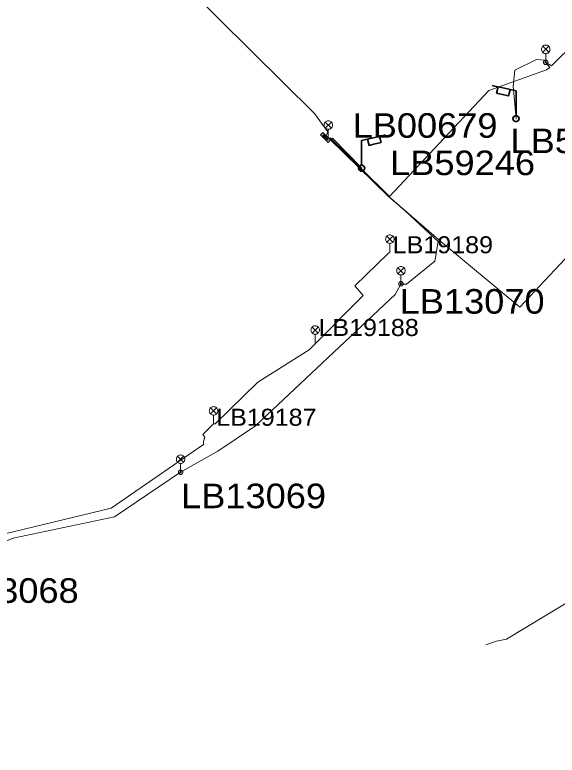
# Model space of a CAD drawing. Extents: x -688049 to -687261, y -973611 to -973038.
# Drawn here: x -687529.7 to -687482, y -973591.4 to -973526.2 of the extents above; entities that cross this region are included whole.
import ezdxf

# ---------------------------------------------------------------- set-up
doc = ezdxf.new("R2010")
doc.units = 0
doc.header["$LTSCALE"] = 0.87
doc.linetypes.add('LONG_DASH_SHORT_DASH', pattern=[9.9, 6, -1.2, 1.5, -1.2])
doc.layers.add('1', color=7, linetype='Continuous', lineweight=13)

msp = doc.modelspace()

# ---------------------------------------------------------------- hatches: boundary and pattern name
at = {"layer": '1'}
for points in [[(-687502.608, -973536.55), (-687501.932, -973537.217), (-687502.154, -973537.442), (-687502.83, -973536.776)], [(-687502.561, -973536.774), (-687502.156, -973537.173), (-687502.2, -973537.218), (-687502.606, -973536.819)]]:
    msp.add_hatch(color=256, dxfattribs=at).paths.add_polyline_path(points)

# ---------------------------------------------------------------- linework, layer by layer
for p, q in [((-687483.245, -973528.965), (-687482.715, -973529.495)), ((-687483.245, -973529.495), (-687482.715, -973528.965)), ((-687482.98, -973530.38), (-687482.98, -973529.605)), ((-687502.396, -973535.64), (-687501.866, -973536.17)), ((-687502.396, -973536.17), (-687501.866, -973535.64)), ((-687502.131, -973537.055), (-687502.131, -973536.28)), ((-687496.974, -973545.689), (-687496.444, -973546.219)), ((-687496.974, -973546.219), (-687496.444, -973545.689)), ((-687496.709, -973547.104), (-687496.709, -973546.329)), ((-687495.995, -973548.475), (-687495.465, -973549.005)), ((-687495.995, -973549.005), (-687495.465, -973548.475)), ((-687495.73, -973549.89), (-687495.73, -973549.115)), ((-687503.552, -973553.701), (-687503.022, -973554.231)), ((-687503.552, -973554.231), (-687503.022, -973553.701)), ((-687503.287, -973555.116), (-687503.287, -973554.341)), ((-687512.507, -973560.829), (-687511.977, -973561.359)), ((-687512.507, -973561.359), (-687511.977, -973560.829)), ((-687512.242, -973562.244), (-687512.242, -973561.469)), ((-687515.405, -973565.085), (-687514.875, -973565.615)), ((-687515.405, -973565.615), (-687514.875, -973565.085)), ((-687515.14, -973566.5), (-687515.14, -973565.725))]:
    msp.add_line(p, q, dxfattribs=at)
at = {"layer": '1', "lineweight": 35}
for p, q in [((-687485.57, -973535.34), (-687485.624, -973535.34)), ((-687499.224, -973539.7), (-687499.17, -973539.7))]:
    msp.add_line(p, q, dxfattribs=at)
at = {"layer": '1'}
for points in [[(-687467.405, -973515.295), (-687467.405, -973515.662), (-687469.111, -973517.285), (-687472.35, -973520.366), (-687478.189, -973526.459), (-687482.459, -973530.691), (-687482.98, -973530.38)], [(-687517.645, -973521.334), (-687517.314, -973521.125), (-687514.569, -973523.755), (-687503.343, -973534.873), (-687502.167, -973536.514), (-687502.381, -973536.996)], [(-687482.97, -973530.382), (-687482.626, -973530.839), (-687482.904, -973531.048), (-687487.979, -973532.871), (-687496.755, -973542.207), (-687501.975, -973537.02), (-687502.131, -973537.055)], [(-687480.925, -973547.385), (-687481.31, -973547.725), (-687485.252, -973551.938), (-687492.408, -973546.007), (-687496.766, -973542.227), (-687502.006, -973537.076), (-687502.131, -973537.055)], [(-687495.73, -973549.94), (-687495.244, -973549.94), (-687492.742, -973547.903), (-687492.441, -973546.165), (-687495.323, -973543.485), (-687496.865, -973542.174), (-687502.028, -973537.125), (-687502.131, -973537.055)], [(-687503.287, -973555.116), (-687503.226, -973555.116), (-687499.071, -973550.923), (-687499.792, -973550.062), (-687496.828, -973547.19), (-687496.709, -973547.104)], [(-687495.73, -973549.94), (-687496.256, -973550.822), (-687508.558, -973562.417), (-687511.878, -973564.636), (-687515.14, -973566.5)], [(-687512.242, -973562.244), (-687512.091, -973562.244), (-687508.337, -973558.555), (-687503.828, -973555.698), (-687503.28, -973555.178), (-687503.287, -973555.116)], [(-687512.242, -973562.244), (-687513.198, -973563.185), (-687513.014, -973563.421), (-687513.139, -973563.788), (-687513.139, -973564.053), (-687521.25, -973569.673), (-687531.507, -973572.146), (-687537.665, -973575.239), (-687557.082, -973591.297), (-687558.661, -973591.432), (-687559.419, -973591.073), (-687564.028, -973586.264), (-687565.766, -973584.462), (-687569.052, -973581.162), (-687571.096, -973578.384), (-687572.639, -973577), (-687572.732, -973575.503), (-687572.487, -973574.726), (-687571.502, -973574.263), (-687570.41, -973574.56)], [(-687515.14, -973566.5), (-687520.976, -973570.433), (-687529.887, -973572.299), (-687535.528, -973574.583), (-687536.76, -973575.4)], [(-687488.25, -973581.7), (-687487.316, -973581.393), (-687486.449, -973581.213), (-687476.202, -973575.029), (-687473.932, -973573.292), (-687473.59, -973572.32)]]:
    msp.add_lwpolyline(points, dxfattribs=at)
for points in [[(-687482.605, -973529.23), (-687482.611, -973529.165), (-687482.628, -973529.102), (-687482.655, -973529.043), (-687482.693, -973528.989), (-687482.739, -973528.943), (-687482.792, -973528.905), (-687482.852, -973528.878), (-687482.915, -973528.861), (-687482.98, -973528.855), (-687483.045, -973528.861), (-687483.108, -973528.878), (-687483.168, -973528.905), (-687483.221, -973528.943), (-687483.267, -973528.989), (-687483.305, -973529.043), (-687483.332, -973529.102), (-687483.349, -973529.165), (-687483.355, -973529.23), (-687483.349, -973529.295), (-687483.332, -973529.358), (-687483.305, -973529.418), (-687483.267, -973529.471), (-687483.221, -973529.517), (-687483.168, -973529.555), (-687483.108, -973529.582), (-687483.045, -973529.599), (-687482.98, -973529.605), (-687482.915, -973529.599), (-687482.852, -973529.582), (-687482.792, -973529.555), (-687482.739, -973529.517), (-687482.693, -973529.471), (-687482.655, -973529.418), (-687482.628, -973529.358), (-687482.611, -973529.295)], [(-687482.79, -973530.38), (-687482.793, -973530.347), (-687482.801, -973530.315), (-687482.815, -973530.285), (-687482.834, -973530.258), (-687482.858, -973530.234), (-687482.885, -973530.215), (-687482.915, -973530.201), (-687482.947, -973530.193), (-687482.98, -973530.19), (-687483.013, -973530.193), (-687483.045, -973530.201), (-687483.075, -973530.215), (-687483.102, -973530.234), (-687483.126, -973530.258), (-687483.145, -973530.285), (-687483.159, -973530.315), (-687483.167, -973530.347), (-687483.17, -973530.38), (-687483.167, -973530.413), (-687483.159, -973530.445), (-687483.145, -973530.475), (-687483.126, -973530.502), (-687483.102, -973530.526), (-687483.075, -973530.545), (-687483.045, -973530.559), (-687483.013, -973530.567), (-687482.98, -973530.57), (-687482.947, -973530.567), (-687482.915, -973530.559), (-687482.885, -973530.545), (-687482.858, -973530.526), (-687482.834, -973530.502), (-687482.815, -973530.475), (-687482.801, -973530.445), (-687482.793, -973530.413)], [(-687482.93, -973530.38), (-687482.931, -973530.371), (-687482.933, -973530.363), (-687482.937, -973530.355), (-687482.942, -973530.348), (-687482.948, -973530.342), (-687482.955, -973530.337), (-687482.963, -973530.333), (-687482.971, -973530.331), (-687482.98, -973530.33), (-687482.989, -973530.331), (-687482.997, -973530.333), (-687483.005, -973530.337), (-687483.012, -973530.342), (-687483.018, -973530.348), (-687483.023, -973530.355), (-687483.027, -973530.363), (-687483.029, -973530.371), (-687483.03, -973530.38), (-687483.029, -973530.389), (-687483.027, -973530.397), (-687483.023, -973530.405), (-687483.018, -973530.412), (-687483.012, -973530.418), (-687483.005, -973530.423), (-687482.997, -973530.427), (-687482.989, -973530.429), (-687482.98, -973530.43), (-687482.971, -973530.429), (-687482.963, -973530.427), (-687482.955, -973530.423), (-687482.948, -973530.418), (-687482.942, -973530.412), (-687482.937, -973530.405), (-687482.933, -973530.397), (-687482.931, -973530.389)], [(-687501.756, -973535.905), (-687501.762, -973535.84), (-687501.779, -973535.777), (-687501.806, -973535.718), (-687501.844, -973535.664), (-687501.89, -973535.618), (-687501.944, -973535.58), (-687502.003, -973535.553), (-687502.066, -973535.536), (-687502.131, -973535.53), (-687502.196, -973535.536), (-687502.259, -973535.553), (-687502.318, -973535.58), (-687502.372, -973535.618), (-687502.418, -973535.664), (-687502.456, -973535.718), (-687502.483, -973535.777), (-687502.5, -973535.84), (-687502.506, -973535.905), (-687502.5, -973535.97), (-687502.483, -973536.033), (-687502.456, -973536.093), (-687502.418, -973536.146), (-687502.372, -973536.192), (-687502.318, -973536.23), (-687502.259, -973536.257), (-687502.196, -973536.274), (-687502.131, -973536.28), (-687502.066, -973536.274), (-687502.003, -973536.257), (-687501.944, -973536.23), (-687501.89, -973536.192), (-687501.844, -973536.146), (-687501.806, -973536.093), (-687501.779, -973536.033), (-687501.762, -973535.97)], [(-687502.608, -973536.55), (-687501.932, -973537.217), (-687502.154, -973537.442), (-687502.83, -973536.776)], [(-687502.608, -973536.55), (-687501.932, -973537.217), (-687502.154, -973537.442), (-687502.83, -973536.776)], [(-687502.561, -973536.774), (-687502.156, -973537.173), (-687502.2, -973537.218), (-687502.606, -973536.819)], [(-687496.334, -973545.954), (-687496.34, -973545.889), (-687496.357, -973545.826), (-687496.384, -973545.766), (-687496.422, -973545.713), (-687496.468, -973545.667), (-687496.522, -973545.629), (-687496.581, -973545.602), (-687496.644, -973545.585), (-687496.709, -973545.579), (-687496.774, -973545.585), (-687496.837, -973545.602), (-687496.896, -973545.629), (-687496.95, -973545.667), (-687496.996, -973545.713), (-687497.034, -973545.766), (-687497.061, -973545.826), (-687497.078, -973545.889), (-687497.084, -973545.954), (-687497.078, -973546.019), (-687497.061, -973546.082), (-687497.034, -973546.142), (-687496.996, -973546.195), (-687496.95, -973546.241), (-687496.896, -973546.279), (-687496.837, -973546.306), (-687496.774, -973546.323), (-687496.709, -973546.329), (-687496.644, -973546.323), (-687496.581, -973546.306), (-687496.522, -973546.279), (-687496.468, -973546.241), (-687496.422, -973546.195), (-687496.384, -973546.142), (-687496.357, -973546.082), (-687496.34, -973546.019)], [(-687495.355, -973548.74), (-687495.361, -973548.675), (-687495.378, -973548.612), (-687495.405, -973548.552), (-687495.443, -973548.499), (-687495.489, -973548.453), (-687495.542, -973548.415), (-687495.602, -973548.388), (-687495.665, -973548.371), (-687495.73, -973548.365), (-687495.795, -973548.371), (-687495.858, -973548.388), (-687495.918, -973548.415), (-687495.971, -973548.453), (-687496.017, -973548.499), (-687496.055, -973548.552), (-687496.082, -973548.612), (-687496.099, -973548.675), (-687496.105, -973548.74), (-687496.099, -973548.805), (-687496.082, -973548.868), (-687496.055, -973548.928), (-687496.017, -973548.981), (-687495.971, -973549.027), (-687495.918, -973549.065), (-687495.858, -973549.092), (-687495.795, -973549.109), (-687495.73, -973549.115), (-687495.665, -973549.109), (-687495.602, -973549.092), (-687495.542, -973549.065), (-687495.489, -973549.027), (-687495.443, -973548.981), (-687495.405, -973548.928), (-687495.378, -973548.868), (-687495.361, -973548.805)], [(-687495.54, -973549.89), (-687495.543, -973549.857), (-687495.551, -973549.825), (-687495.565, -973549.795), (-687495.584, -973549.768), (-687495.608, -973549.744), (-687495.635, -973549.725), (-687495.665, -973549.711), (-687495.697, -973549.703), (-687495.73, -973549.7), (-687495.763, -973549.703), (-687495.795, -973549.711), (-687495.825, -973549.725), (-687495.852, -973549.744), (-687495.876, -973549.768), (-687495.895, -973549.795), (-687495.909, -973549.825), (-687495.917, -973549.857), (-687495.92, -973549.89), (-687495.917, -973549.923), (-687495.909, -973549.955), (-687495.895, -973549.985), (-687495.876, -973550.012), (-687495.852, -973550.036), (-687495.825, -973550.055), (-687495.795, -973550.069), (-687495.763, -973550.077), (-687495.73, -973550.08), (-687495.697, -973550.077), (-687495.665, -973550.069), (-687495.635, -973550.055), (-687495.608, -973550.036), (-687495.584, -973550.012), (-687495.565, -973549.985), (-687495.551, -973549.955), (-687495.543, -973549.923)], [(-687495.68, -973549.89), (-687495.681, -973549.881), (-687495.683, -973549.873), (-687495.687, -973549.865), (-687495.692, -973549.858), (-687495.698, -973549.852), (-687495.705, -973549.847), (-687495.713, -973549.843), (-687495.721, -973549.841), (-687495.73, -973549.84), (-687495.739, -973549.841), (-687495.747, -973549.843), (-687495.755, -973549.847), (-687495.762, -973549.852), (-687495.768, -973549.858), (-687495.773, -973549.865), (-687495.777, -973549.873), (-687495.779, -973549.881), (-687495.78, -973549.89), (-687495.779, -973549.899), (-687495.777, -973549.907), (-687495.773, -973549.915), (-687495.768, -973549.922), (-687495.762, -973549.928), (-687495.755, -973549.933), (-687495.747, -973549.937), (-687495.739, -973549.939), (-687495.73, -973549.94), (-687495.721, -973549.939), (-687495.713, -973549.937), (-687495.705, -973549.933), (-687495.698, -973549.928), (-687495.692, -973549.922), (-687495.687, -973549.915), (-687495.683, -973549.907), (-687495.681, -973549.899)], [(-687502.912, -973553.966), (-687502.918, -973553.901), (-687502.935, -973553.838), (-687502.962, -973553.778), (-687503, -973553.725), (-687503.046, -973553.679), (-687503.1, -973553.641), (-687503.159, -973553.614), (-687503.222, -973553.597), (-687503.287, -973553.591), (-687503.352, -973553.597), (-687503.415, -973553.614), (-687503.474, -973553.641), (-687503.528, -973553.679), (-687503.574, -973553.725), (-687503.612, -973553.778), (-687503.639, -973553.838), (-687503.656, -973553.901), (-687503.662, -973553.966), (-687503.656, -973554.031), (-687503.639, -973554.094), (-687503.612, -973554.154), (-687503.574, -973554.207), (-687503.528, -973554.253), (-687503.474, -973554.291), (-687503.415, -973554.318), (-687503.352, -973554.335), (-687503.287, -973554.341), (-687503.222, -973554.335), (-687503.159, -973554.318), (-687503.1, -973554.291), (-687503.046, -973554.253), (-687503, -973554.207), (-687502.962, -973554.154), (-687502.935, -973554.094), (-687502.918, -973554.031)], [(-687511.867, -973561.094), (-687511.873, -973561.029), (-687511.89, -973560.966), (-687511.917, -973560.906), (-687511.955, -973560.853), (-687512.001, -973560.807), (-687512.054, -973560.769), (-687512.114, -973560.742), (-687512.177, -973560.725), (-687512.242, -973560.719), (-687512.307, -973560.725), (-687512.37, -973560.742), (-687512.43, -973560.769), (-687512.483, -973560.807), (-687512.529, -973560.853), (-687512.567, -973560.906), (-687512.594, -973560.966), (-687512.611, -973561.029), (-687512.617, -973561.094), (-687512.611, -973561.159), (-687512.594, -973561.222), (-687512.567, -973561.282), (-687512.529, -973561.335), (-687512.483, -973561.381), (-687512.43, -973561.419), (-687512.37, -973561.446), (-687512.307, -973561.463), (-687512.242, -973561.469), (-687512.177, -973561.463), (-687512.114, -973561.446), (-687512.054, -973561.419), (-687512.001, -973561.381), (-687511.955, -973561.335), (-687511.917, -973561.282), (-687511.89, -973561.222), (-687511.873, -973561.159)], [(-687514.765, -973565.35), (-687514.771, -973565.285), (-687514.788, -973565.222), (-687514.815, -973565.163), (-687514.853, -973565.109), (-687514.899, -973565.063), (-687514.952, -973565.025), (-687515.012, -973564.998), (-687515.075, -973564.981), (-687515.14, -973564.975), (-687515.205, -973564.981), (-687515.268, -973564.998), (-687515.328, -973565.025), (-687515.381, -973565.063), (-687515.427, -973565.109), (-687515.465, -973565.163), (-687515.492, -973565.222), (-687515.509, -973565.285), (-687515.515, -973565.35), (-687515.509, -973565.415), (-687515.492, -973565.478), (-687515.465, -973565.538), (-687515.427, -973565.591), (-687515.381, -973565.637), (-687515.328, -973565.675), (-687515.268, -973565.702), (-687515.205, -973565.719), (-687515.14, -973565.725), (-687515.075, -973565.719), (-687515.012, -973565.702), (-687514.952, -973565.675), (-687514.899, -973565.637), (-687514.853, -973565.591), (-687514.815, -973565.538), (-687514.788, -973565.478), (-687514.771, -973565.415)], [(-687514.95, -973566.5), (-687514.953, -973566.467), (-687514.961, -973566.435), (-687514.975, -973566.405), (-687514.994, -973566.378), (-687515.018, -973566.354), (-687515.045, -973566.335), (-687515.075, -973566.321), (-687515.107, -973566.313), (-687515.14, -973566.31), (-687515.173, -973566.313), (-687515.205, -973566.321), (-687515.235, -973566.335), (-687515.262, -973566.354), (-687515.286, -973566.378), (-687515.305, -973566.405), (-687515.319, -973566.435), (-687515.327, -973566.467), (-687515.33, -973566.5), (-687515.327, -973566.533), (-687515.319, -973566.565), (-687515.305, -973566.595), (-687515.286, -973566.622), (-687515.262, -973566.646), (-687515.235, -973566.665), (-687515.205, -973566.679), (-687515.173, -973566.687), (-687515.14, -973566.69), (-687515.107, -973566.687), (-687515.075, -973566.679), (-687515.045, -973566.665), (-687515.018, -973566.646), (-687514.994, -973566.622), (-687514.975, -973566.595), (-687514.961, -973566.565), (-687514.953, -973566.533)], [(-687515.09, -973566.5), (-687515.091, -973566.491), (-687515.093, -973566.483), (-687515.097, -973566.475), (-687515.102, -973566.468), (-687515.108, -973566.462), (-687515.115, -973566.457), (-687515.123, -973566.453), (-687515.131, -973566.451), (-687515.14, -973566.45), (-687515.149, -973566.451), (-687515.157, -973566.453), (-687515.165, -973566.457), (-687515.172, -973566.462), (-687515.178, -973566.468), (-687515.183, -973566.475), (-687515.187, -973566.483), (-687515.189, -973566.491), (-687515.19, -973566.5), (-687515.189, -973566.509), (-687515.187, -973566.517), (-687515.183, -973566.525), (-687515.178, -973566.532), (-687515.172, -973566.538), (-687515.165, -973566.543), (-687515.157, -973566.547), (-687515.149, -973566.549), (-687515.14, -973566.55), (-687515.131, -973566.549), (-687515.123, -973566.547), (-687515.115, -973566.543), (-687515.108, -973566.538), (-687515.102, -973566.532), (-687515.097, -973566.525), (-687515.093, -973566.517), (-687515.091, -973566.509)]]:
    msp.add_lwpolyline(points, close=True, dxfattribs=at)
at = {"layer": '1', "linetype": 'LONG_DASH_SHORT_DASH'}
for points in [[(-687483.07, -973530.19), (-687483.8, -973530.14), (-687485.7, -973531.06), (-687485.86, -973532.47), (-687485.57, -973535.34)], [(-687501.89, -973537.2), (-687501.76, -973537.07), (-687499.17, -973539.7)]]:
    msp.add_lwpolyline(points, dxfattribs=at)
at = {"layer": '1', "lineweight": 35}
for points in [[(-687485.597, -973535.085), (-687485.684, -973535.085), (-687485.819, -973535.183), (-687485.873, -973535.34), (-687485.819, -973535.497), (-687485.684, -973535.595), (-687485.516, -973535.595), (-687485.38, -973535.497), (-687485.326, -973535.34), (-687485.38, -973535.183), (-687485.516, -973535.085), (-687485.597, -973535.085), (-687485.597, -973534.397), (-687485.597, -973533.709), (-687485.597, -973533.021), (-687485.597, -973532.902), (-687486.231, -973532.755), (-687486.865, -973532.609), (-687487.499, -973532.463), (-687487.71, -973532.414)], [(-687487.168, -973532.549), (-687487.304, -973533.091), (-687486.67, -973533.238), (-687486.247, -973533.335), (-687486.112, -973532.793)], [(-687499.197, -973539.445), (-687499.11, -973539.445), (-687498.975, -973539.543), (-687498.921, -973539.7), (-687498.975, -973539.857), (-687499.11, -973539.955), (-687499.278, -973539.955), (-687499.414, -973539.857), (-687499.468, -973539.7), (-687499.414, -973539.543), (-687499.278, -973539.445), (-687499.197, -973539.445), (-687499.197, -973538.757), (-687499.197, -973538.069), (-687499.197, -973537.381), (-687499.197, -973537.262), (-687498.563, -973537.115), (-687497.929, -973536.969), (-687497.295, -973536.823), (-687497.084, -973536.774)], [(-687497.626, -973536.909), (-687497.49, -973537.451), (-687498.124, -973537.598), (-687498.547, -973537.695), (-687498.682, -973537.153)]]:
    msp.add_lwpolyline(points, dxfattribs=at)

# ---------------------------------------------------------------- texts
at = {"layer": '1', "width": 1.1}
for s, height, p in [('LB00679', 2.167, (-687499.991, -973537.028)), ('LB59245', 2.168, (-687486.084, -973538.381)), ('LB59246', 2.168, (-687496.69, -973540.319)), ('LB19189', 1.5, (-687496.458, -973547.203)), ('LB13070', 2.167, (-687495.844, -973552.526)), ('LB19188', 1.5, (-687503, -973554.494)), ('LB19187', 1.5, (-687512.006, -973562.4)), ('LB13069', 2.167, (-687515.097, -973569.668)), ('LB13068', 2.167, (-687536.884, -973578.009))]:
    msp.add_text(s, height=height, dxfattribs=at).set_placement(p)

doc.saveas('drawing.dxf')
